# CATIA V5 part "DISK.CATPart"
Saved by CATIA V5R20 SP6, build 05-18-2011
Part number: DISK
Bounding box of the stored display mesh (mm): x -134.28 to 162.72, y -829.34 to -775.339, z -29.5 to 267.5
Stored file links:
  C:\V5_education\Assemble Design\CATProduct\Disk brake\DISK.CATPart
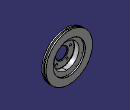
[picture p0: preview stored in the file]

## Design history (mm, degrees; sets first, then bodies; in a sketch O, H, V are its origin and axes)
Body1 "PartBody ( *SOL65 - wsp *MASTER -  )" (main body)
  Solid1 "Solid.1 (  with JELE 4667 : from *SOL65 - wsp *MASTER -  ) ( Brep from *SOL65 )": solid without history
